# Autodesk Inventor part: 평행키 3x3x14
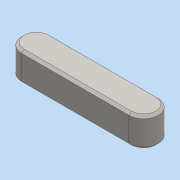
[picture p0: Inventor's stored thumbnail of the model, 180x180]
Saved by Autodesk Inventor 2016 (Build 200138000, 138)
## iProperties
Created: 2024-09
Part Number: 평행키 3x3x14
Material: 일반
Description: 키 및 해당 키홈
Document SubType Name: Modeling
Designer: pc-7
Density: 1 g/cm^3
Appearance: 기본값
Author: jhkim
Sending System: Autodesk Inventor 2025
Preprocessor: ST-DEVELOPER v20
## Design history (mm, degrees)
node "평행키 3x3x141"
node "솔리드1"
body "Solid1"
